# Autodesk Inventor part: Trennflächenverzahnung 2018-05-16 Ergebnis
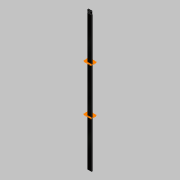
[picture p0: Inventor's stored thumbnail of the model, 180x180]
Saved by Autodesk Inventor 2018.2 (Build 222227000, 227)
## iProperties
Created: 2018-05
Part Number: Trennflächenverzahnung 2018-05-16 Ergebnis
Material: ---
Document SubType Name: Modeling
Designer: Roland
Appearance: grau
Author: Roland
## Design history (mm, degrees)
node "Blöcke"
  sketch "Rechteck abgerundet"
    geometry: L1 (182.926, 40.686)-(222.735, 40.686); L2 (229.51, 47.461)-(229.51, 80.56); L3 (176.151, 47.461)-(176.151, 80.56); L4 (182.926, 87.335)-(222.735, 87.335); A1 r 6.775 centre (222.735, 47.461) between (222.735, 40.686) and (229.51, 47.461); A2 r 6.775 centre (222.735, 80.56) between (229.51, 80.56) and (222.735, 87.335); A3 r 6.775 centre (182.926, 47.461) between (176.151, 47.461) and (182.926, 40.686); A4 r 6.775 centre (182.926, 80.56) between (182.926, 87.335) and (176.151, 80.56); 1 further point
    constraints: 8 end point, 8 point on circle, 8 tangent, 4 centre point, 3 equal radius, 3 perpendicular, 1 coincident
derived "Trennflächenverzahnung 2018-05-16.iam"
feature "Trennen1"
  node "Volumen1"
feature "Trennen2"
  node "Volumen4"
node "RE-ENG-043744komplett.ipt:1"
node "Trennflächenverzahnung 2018-05-16.ipt:1"
node "Volumen2"
node "Fläche1"
node "Trennflächenverzahnung 2018-05-16.ipt:2"
node "Volumen3"
node "Fläche2"
feature "Fläche34::Abgeleitet"
feature "Fläche34::Abgeleitet_1"
node "Volumen5"
node "Volumen6"
node "Volumen7"
